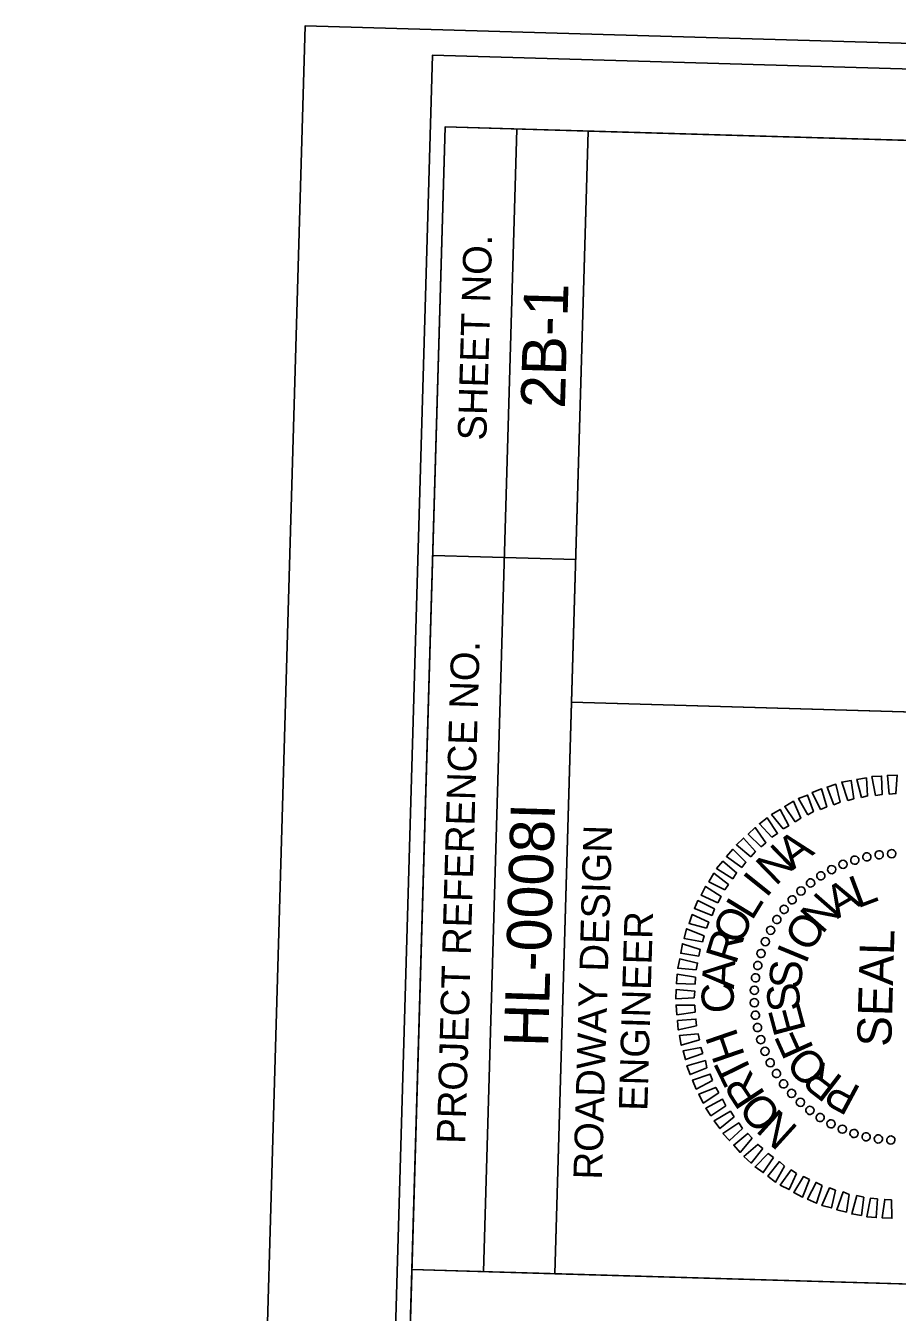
# Model space of a CAD drawing. Extents: x 2097422 to 2097881, y 685612 to 686386.
# Drawn here: x 2097421.7 to 2097482.8, y 686208.2 to 686298.2 of the extents above; entities that cross this region are included whole.
import ezdxf

# ---------------------------------------------------------------- set-up
doc = ezdxf.new("R2010")
doc.units = 0
for name, color, linetype in [('Scratch_Level_0', 7, 'Continuous'), ('Sheet Data Field CELL', 7, 'Continuous'), ('Sheet Layout Plan Border', 7, 'Continuous'), ('Sheet PE Seal Cell', 7, 'Continuous'), ('Sheet Plot Border Inside CELL', 7, 'Continuous'), ('Sheet Plot Border Outside CELL', 7, 'Continuous'), ('Sheet Profile CELL', 7, 'Continuous')]:
    doc.layers.add(name, color=color, linetype=linetype)

msp = doc.modelspace()

# ---------------------------------------------------------------- linework, layer by layer
at = {"layer": 'Scratch_Level_0'}
msp.add_lwpolyline([(2097511.345, 685744.127), (2097439.862, 685904.988), (2097448.762, 686211.158), (2097523.653, 686208.981), (2097524.098, 686224.269), (2097869.03, 686214.241), (2097857.522, 685818.411), (2097708.276, 685751.241), (2097678.123, 685684.291), (2097536.101, 685688.42)], close=True, dxfattribs=at)
at = {"layer": 'Sheet Layout Plan Border'}
msp.add_lwpolyline([(2097566.717, 685687.53), (2097536.101, 685688.42), (2097439.862, 685904.988), (2097448.762, 686211.158), (2097459.26, 686210.853), (2097523.653, 686208.981), (2097524.098, 686224.269), (2097869.03, 686214.241), (2097857.522, 685818.411)], close=True, dxfattribs=at)
at = {"layer": 'Sheet PE Seal Cell'}
for p, q in [((2097480.61, 686240.053), (2097480.61, 686240.053)), ((2097481.495, 686240.187), (2097481.495, 686240.187)), ((2097482.358, 686240.282), (2097482.358, 686240.282)), ((2097478.163, 686239.164), (2097478.163, 686239.164)), ((2097478.955, 686239.541), (2097478.955, 686239.541)), ((2097479.764, 686239.838), (2097479.764, 686239.838)), ((2097476.676, 686238.247), (2097476.676, 686238.247)), ((2097477.39, 686238.726), (2097477.39, 686238.726)), ((2097475.999, 686237.666), (2097475.999, 686237.666)), ((2097475.381, 686237.064), (2097475.381, 686237.064)), ((2097474.3, 686235.675), (2097474.3, 686235.675)), ((2097474.821, 686236.38), (2097474.821, 686236.38)), ((2097473.878, 686234.907), (2097473.878, 686234.907)), ((2097473.495, 686234.117), (2097473.495, 686234.117)), ((2097473.19, 686233.286), (2097473.19, 686233.286)), ((2097472.986, 686232.451), (2097472.986, 686232.451)), ((2097472.821, 686231.596), (2097472.821, 686231.596)), ((2097472.736, 686230.718), (2097472.736, 686230.718)), ((2097472.73, 686229.838), (2097472.73, 686229.838)), ((2097472.825, 686228.975), (2097472.825, 686228.975)), ((2097472.959, 686228.09), (2097472.959, 686228.09)), ((2097473.175, 686227.244), (2097473.175, 686227.244)), ((2097473.472, 686226.435), (2097473.472, 686226.435)), ((2097473.849, 686225.644), (2097473.849, 686225.644)), ((2097474.286, 686224.87), (2097474.286, 686224.87)), ((2097474.766, 686224.156), (2097474.766, 686224.156)), ((2097475.346, 686223.479), (2097475.346, 686223.479)), ((2097475.949, 686222.861), (2097475.949, 686222.861)), ((2097476.633, 686222.301), (2097476.633, 686222.301)), ((2097477.338, 686221.781), (2097477.338, 686221.781)), ((2097478.106, 686221.358), (2097478.106, 686221.358)), ((2097478.895, 686220.975), (2097478.895, 686220.975)), ((2097479.727, 686220.671), (2097479.727, 686220.671)), ((2097480.561, 686220.466), (2097480.561, 686220.466)), ((2097481.417, 686220.301), (2097481.417, 686220.301)), ((2097482.295, 686220.216), (2097482.295, 686220.216))]:
    msp.add_line(p, q, dxfattribs=at)
for points in [[(2097480.251, 686244.205), (2097479.908, 686245.476), (2097480.591, 686245.576), (2097480.674, 686244.313)], [(2097481.216, 686244.357), (2097480.973, 686245.665), (2097481.655, 686245.705), (2097481.698, 686244.423)], [(2097482.179, 686244.449), (2097482.057, 686245.754), (2097482.737, 686245.774), (2097482.66, 686244.475)], [(2097477.365, 686243.369), (2097476.8, 686244.566), (2097477.447, 686244.807), (2097477.811, 686243.556)], [(2097478.315, 686243.701), (2097477.831, 686244.936), (2097478.457, 686245.138), (2097478.741, 686243.889)], [(2097479.284, 686243.993), (2097478.862, 686245.286), (2097479.525, 686245.387), (2097479.708, 686244.121)], [(2097475.599, 686242.5), (2097474.87, 686243.581), (2097475.481, 686243.944), (2097476.007, 686242.768)], [(2097476.494, 686242.994), (2097475.827, 686244.134), (2097476.454, 686244.376), (2097476.881, 686243.223)], [(2097473.967, 686241.427), (2097473.094, 686242.373), (2097473.646, 686242.777), (2097474.375, 686241.695)], [(2097474.764, 686242.004), (2097473.953, 686243.008), (2097474.544, 686243.371), (2097475.151, 686242.233)], [(2097473.227, 686240.748), (2097472.313, 686241.635), (2097472.806, 686242.101), (2097473.556, 686241.039)], [(2097472.507, 686240.049), (2097471.491, 686240.898), (2097471.985, 686241.364), (2097472.818, 686240.42)], [(2097471.865, 686239.307), (2097470.787, 686240.079), (2097471.242, 686240.586), (2097472.156, 686239.679)], [(2097471.241, 686238.505), (2097470.102, 686239.238), (2097470.537, 686239.746), (2097471.494, 686238.938)], [(2097470.679, 686237.741), (2097469.555, 686238.314), (2097469.912, 686238.904), (2097470.93, 686238.114)], [(2097470.192, 686236.835), (2097469.027, 686237.369), (2097469.325, 686237.98), (2097470.425, 686237.268)], [(2097469.786, 686235.946), (2097468.54, 686236.442), (2097468.796, 686236.995), (2097469.94, 686236.402)], [(2097469.4, 686235.057), (2097468.17, 686235.393), (2097468.388, 686236.007), (2097469.552, 686235.473)], [(2097469.113, 686234.105), (2097467.819, 686234.342), (2097467.999, 686235.017), (2097469.225, 686234.522)], [(2097468.863, 686233.092), (2097467.589, 686233.309), (2097467.708, 686233.965), (2097468.937, 686233.57)], [(2097468.675, 686232.137), (2097467.378, 686232.254), (2097467.517, 686232.911), (2097468.769, 686232.614)], [(2097468.586, 686231.139), (2097467.287, 686231.177), (2097467.326, 686231.836), (2097468.62, 686231.618)], [(2097468.538, 686230.18), (2097467.236, 686230.118), (2097467.275, 686230.777), (2097468.572, 686230.659)], [(2097468.609, 686229.177), (2097467.323, 686228.995), (2097467.263, 686229.677), (2097468.563, 686229.659)], [(2097468.701, 686228.214), (2097467.412, 686227.932), (2097467.372, 686228.593), (2097468.655, 686228.696)], [(2097468.893, 686227.248), (2097467.622, 686226.865), (2097467.501, 686227.549), (2097468.805, 686227.671)], [(2097469.125, 686226.281), (2097467.912, 686225.856), (2097467.75, 686226.481), (2097468.997, 686226.705)], [(2097469.417, 686225.292), (2097468.242, 686224.806), (2097468.02, 686225.413), (2097469.311, 686225.795)], [(2097469.811, 686224.4), (2097468.673, 686223.793), (2097468.411, 686224.421), (2097469.644, 686224.845)], [(2097470.266, 686223.527), (2097469.165, 686222.818), (2097468.863, 686223.447), (2097470.037, 686223.914)], [(2097470.74, 686222.633), (2097469.699, 686221.923), (2097469.334, 686222.453), (2097470.513, 686223.079)], [(2097471.318, 686221.855), (2097470.333, 686221.024), (2097469.929, 686221.576), (2097471.069, 686222.243)], [(2097471.914, 686221.038), (2097471.009, 686220.184), (2097470.543, 686220.677), (2097471.645, 686221.426)], [(2097472.595, 686220.358), (2097471.745, 686219.362), (2097471.3, 686219.875), (2097472.284, 686220.687)], [(2097473.334, 686219.636), (2097472.524, 686218.619), (2097472.017, 686219.074), (2097472.982, 686219.926)], [(2097474.076, 686219.014), (2097473.365, 686217.954), (2097472.796, 686218.351), (2097473.704, 686219.285)], [(2097474.858, 686218.391), (2097474.226, 686217.289), (2097473.678, 686217.705), (2097474.508, 686218.721)], [(2097475.704, 686217.886), (2097475.171, 686216.761), (2097474.56, 686217.079), (2097475.331, 686218.137)], [(2097476.612, 686217.46), (2097476.116, 686216.234), (2097475.505, 686216.552), (2097476.178, 686217.672)], [(2097477.48, 686217.034), (2097477.084, 686215.805), (2097476.472, 686216.083), (2097477.067, 686217.266)], [(2097478.431, 686216.707), (2097478.135, 686215.475), (2097477.479, 686215.634), (2097478.016, 686216.879)], [(2097479.383, 686216.419), (2097479.187, 686215.184), (2097478.511, 686215.344), (2097478.968, 686216.591)], [(2097480.398, 686216.229), (2097480.241, 686214.953), (2097479.563, 686215.053), (2097479.921, 686216.343)], [(2097481.355, 686216.101), (2097481.277, 686214.803), (2097480.618, 686214.862), (2097480.876, 686216.155)], [(2097482.354, 686216.052), (2097482.376, 686214.751), (2097481.696, 686214.771), (2097481.874, 686216.066)]]:
    msp.add_lwpolyline(points, close=True, dxfattribs=at)
for centre, major_axis in [((2097479.777, 686239.823), (-0.086, 0.275)), ((2097480.623, 686240.047), (-0.062, 0.281)), ((2097481.485, 686240.196), (-0.037, 0.286)), ((2097482.357, 686240.27), (-0.012, 0.288)), ((2097478.16, 686239.158), (-0.132, 0.256)), ((2097478.954, 686239.526), (-0.109, 0.266)), ((2097476.682, 686238.223), (-0.175, 0.229)), ((2097477.4, 686238.723), (-0.154, 0.243)), ((2097475.389, 686237.045), (-0.212, 0.195)), ((2097476.01, 686237.662), (-0.194, 0.213)), ((2097474.825, 686236.376), (-0.228, 0.176)), ((2097474.321, 686235.661), (-0.242, 0.155)), ((2097473.881, 686234.904), (-0.255, 0.134)), ((2097473.509, 686234.112), (-0.266, 0.111)), ((2097473.207, 686233.291), (-0.274, 0.087)), ((2097472.978, 686232.446), (-0.281, 0.063)), ((2097472.824, 686231.584), (-0.285, 0.038)), ((2097472.743, 686229.838), (-0.288, -0.012)), ((2097472.745, 686230.713), (-0.288, 0.013)), ((2097472.816, 686228.966), (-0.286, -0.037)), ((2097472.966, 686228.103), (-0.281, -0.062)), ((2097473.19, 686227.257), (-0.275, -0.086)), ((2097473.487, 686226.434), (-0.266, -0.109)), ((2097473.854, 686225.64), (-0.256, -0.132)), ((2097474.29, 686224.881), (-0.243, -0.154)), ((2097474.79, 686224.162), (-0.229, -0.175)), ((2097475.35, 686223.49), (-0.213, -0.194)), ((2097475.967, 686222.87), (-0.195, -0.212)), ((2097476.636, 686222.305), (-0.176, -0.228)), ((2097477.352, 686221.801), (-0.155, -0.242)), ((2097478.108, 686221.361), (-0.134, -0.255)), ((2097478.9, 686220.989), (-0.111, -0.266)), ((2097479.722, 686220.687), (-0.087, -0.274)), ((2097480.567, 686220.458), (-0.063, -0.281)), ((2097481.428, 686220.304), (-0.038, -0.285)), ((2097482.3, 686220.225), (-0.013, -0.288))]:
    msp.add_ellipse(centre, major_axis=major_axis, ratio=0.999708, dxfattribs=at)
at = {"layer": 'Sheet Plot Border Inside CELL'}
msp.add_lwpolyline([(2097852.705, 685617.59), (2097872.075, 686283.908), (2097450.213, 686296.172), (2097430.843, 685629.853)], close=True, dxfattribs=at)
at = {"layer": 'Sheet Plot Border Outside CELL'}
msp.add_lwpolyline([(2097861.53, 685612.131), (2097881.104, 686285.446), (2097441.29, 686298.232), (2097421.716, 685624.917)], close=True, dxfattribs=at)
at = {"layer": 'Sheet Profile CELL'}
for p, q in [((2097453.78, 686211.012), (2097456.106, 686290.999)), ((2097450.236, 686261.157), (2097460.232, 686260.866)), ((2097459.941, 686250.87), (2097504.902, 686249.563))]:
    msp.add_line(p, q, dxfattribs=at)
for points in [[(2097451.088, 686291.144), (2097433.653, 685691.398), (2097853.475, 685679.193), (2097870.91, 686278.94)], [(2097448.762, 686211.158), (2097451.088, 686291.144), (2097461.103, 686290.853), (2097458.778, 686210.867)], [(2097459.941, 686250.87), (2097461.103, 686290.853), (2097506.084, 686289.546), (2097504.922, 686249.563)], [(2097458.778, 686210.867), (2097459.941, 686250.87), (2097504.922, 686249.563), (2097503.759, 686209.559)]]:
    msp.add_lwpolyline(points, close=True, dxfattribs=at)

# ---------------------------------------------------------------- texts
at = {"layer": 'Sheet Data Field CELL'}
for s, p in [('2B-1', (2097459.473, 686271.408)), ('HL-0008I', (2097458.293, 686226.713))]:
    msp.add_text(s, height=3.1, rotation=88.33483, dxfattribs=at).set_placement(p)
at = {"layer": 'Sheet PE Seal Cell'}
for s, height, rotation, p in [('A', 2.256, 36.95198, (2097475.44, 686239.103)), ('N', 2.256, 44.15374, (2097474.227, 686237.958)), ('I', 2.255, 51.35497, (2097473.582, 686237.116)), ('A', 2.256, 30.0951, (2097478.563, 686235.691)), ('L', 2.256, 20.73568, (2097479.965, 686236.43)), ('N', 2.255, 48.81144, (2097477.49, 686234.581)), ('L', 2.255, 58.5557, (2097472.575, 686235.525)), ('O', 2.255, 65.75599, (2097471.784, 686233.787)), ('O', 2.255, 58.16831, (2097476.651, 686233.265)), ('R', 2.255, 72.95593, (2097471.446, 686232.456)), ('SEAL', 2.3993, 88.33483, (2097482.325, 686226.738)), ('I', 2.255, 67.52443, (2097476.348, 686232.474)), ('A', 2.255, 87.35515, (2097471.317, 686230.779)), ('S', 2.255, 86.23523, (2097476.018, 686230.763)), ('C', 2.255, 94.5547, (2097471.391, 686229.196)), ('S', 2.255, 95.59044, (2097475.996, 686229.323)), ('E', 2.255, 104.9459, (2097476.376, 686227.931)), ('H', 2.255, 108.95431, (2097472.102, 686226.134)), ('F', 2.255, 114.30186, (2097476.939, 686226.634)), ('O', 2.256, 133.01607, (2097478.08, 686225.28)), ('T', 2.255, 116.1546, (2097472.724, 686224.816)), ('R', 2.256, 142.37448, (2097479.039, 686224.552)), ('R', 2.255, 123.35534, (2097473.564, 686223.431)), ('P', 2.256, 151.73372, (2097480.3, 686223.875)), ('O', 2.255, 130.55657, (2097474.764, 686222.015)), ('N', 2.256, 137.75833, (2097475.896, 686221.062))]:
    msp.add_text(s, height=height, rotation=rotation, dxfattribs=at).set_placement(p)
at = {"layer": 'Sheet Profile CELL'}
for s, height, p in [('SHEET NO.', 2, (2097453.966, 686269.177)), ('PROJECT REFERENCE NO.', 2.00004, (2097452.494, 686219.939)), ('ROADWAY DESIGN', 2.00004, (2097462.066, 686217.439)), ('ENGINEER', 2, (2097465.247, 686222.249))]:
    msp.add_text(s, height=height, rotation=88.33483, dxfattribs=at).set_placement(p)

doc.saveas('drawing.dxf')
